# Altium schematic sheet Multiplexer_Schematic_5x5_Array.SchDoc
size D; SheetNumber: 1; SheetTotal: 1
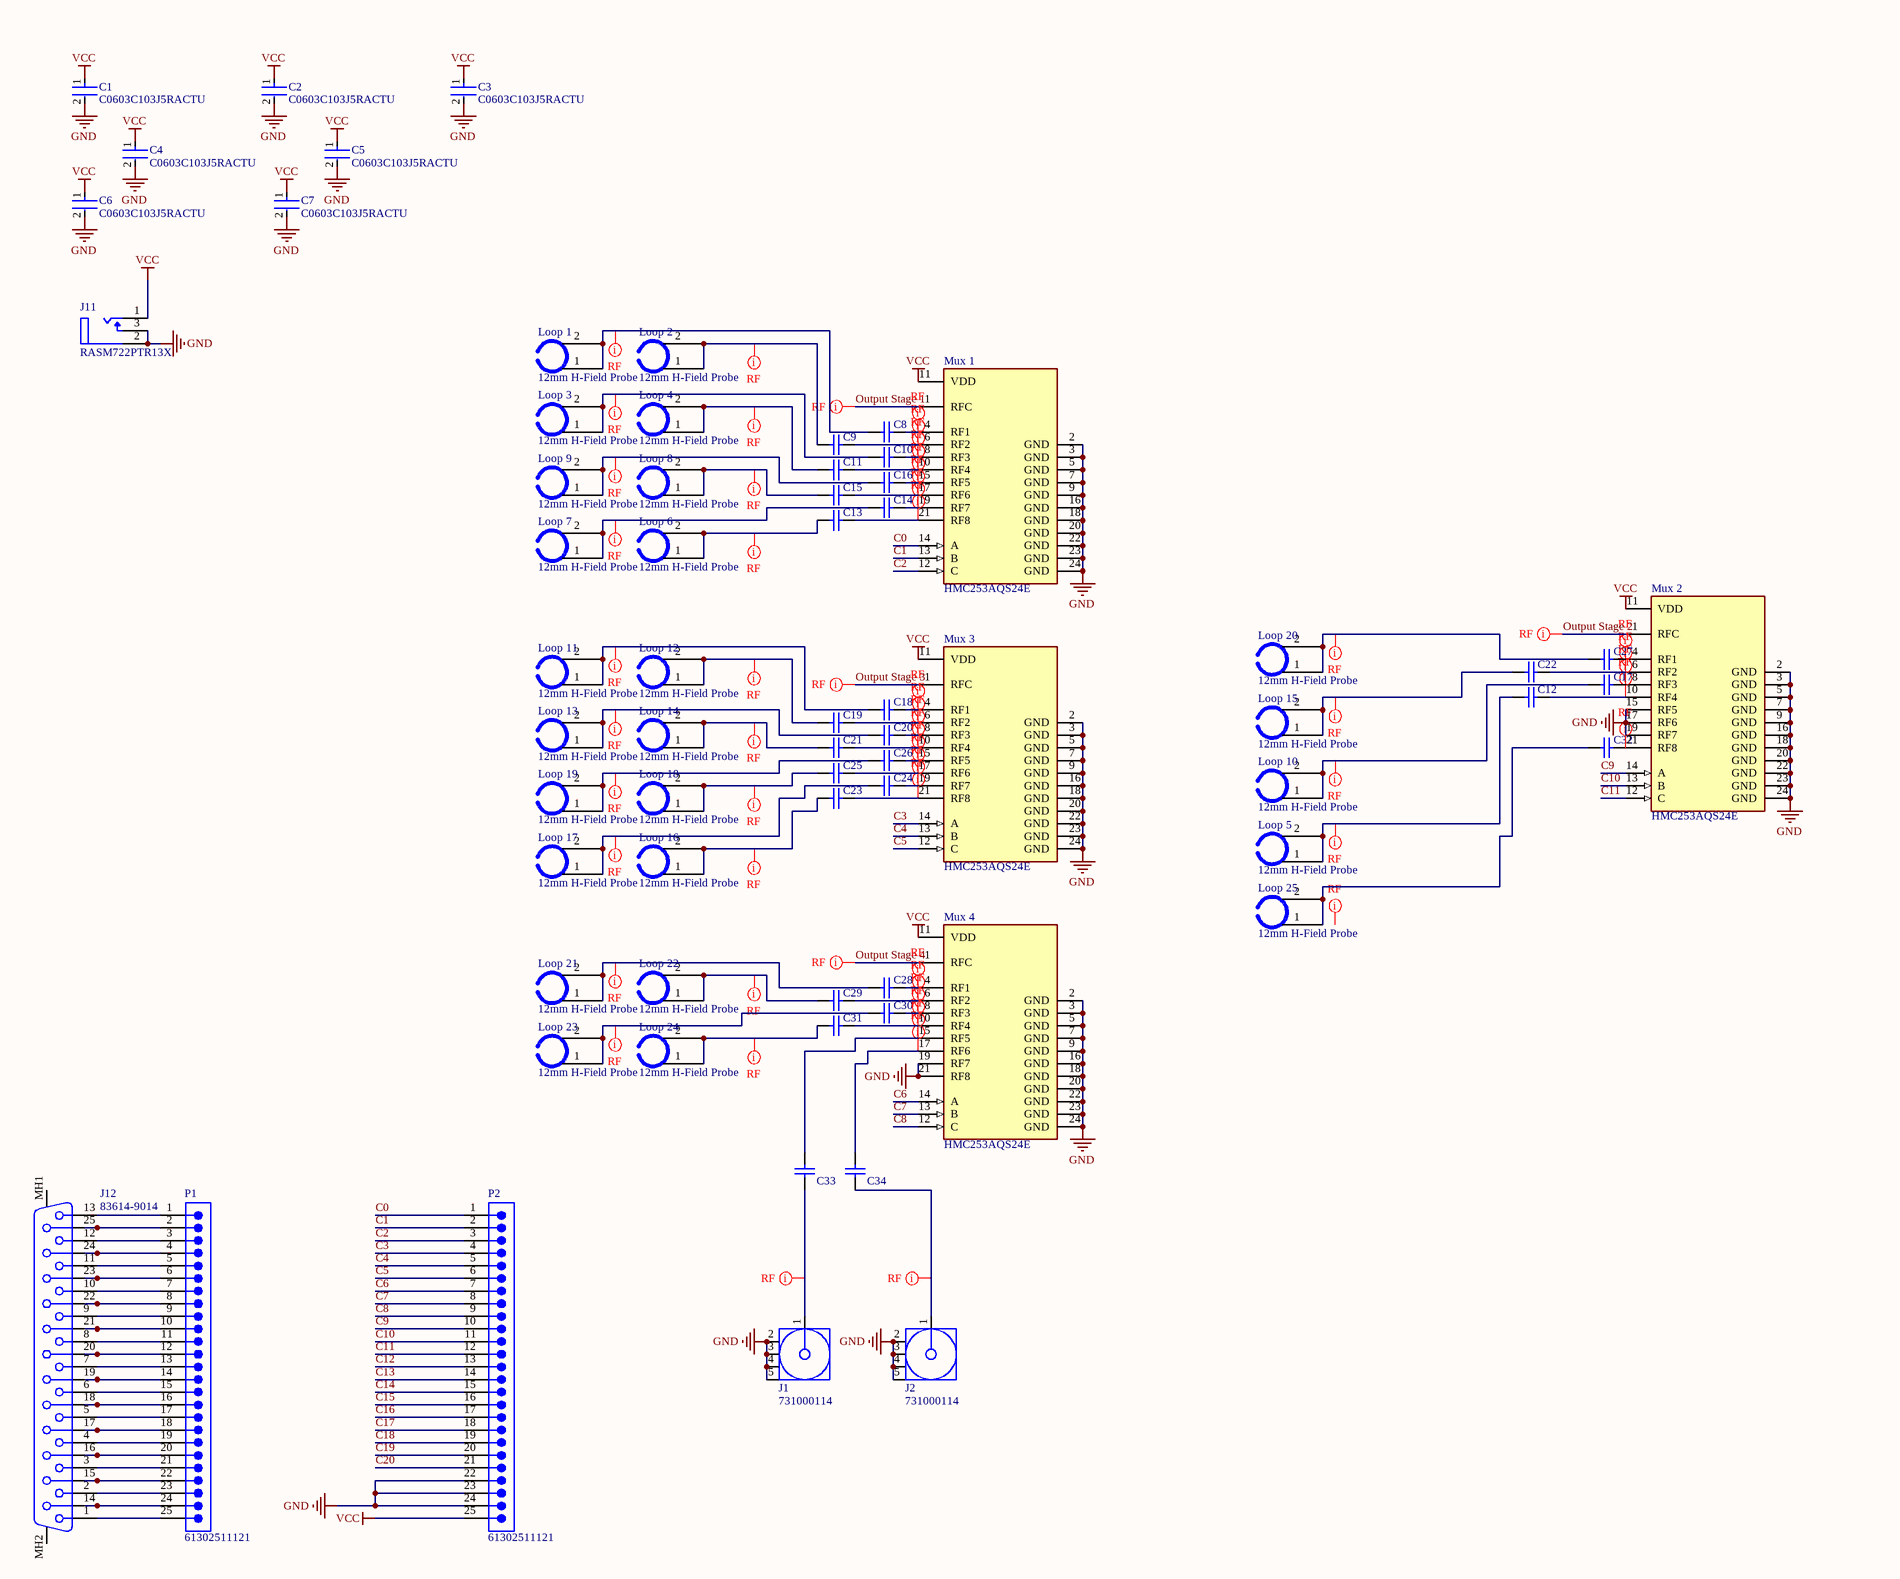
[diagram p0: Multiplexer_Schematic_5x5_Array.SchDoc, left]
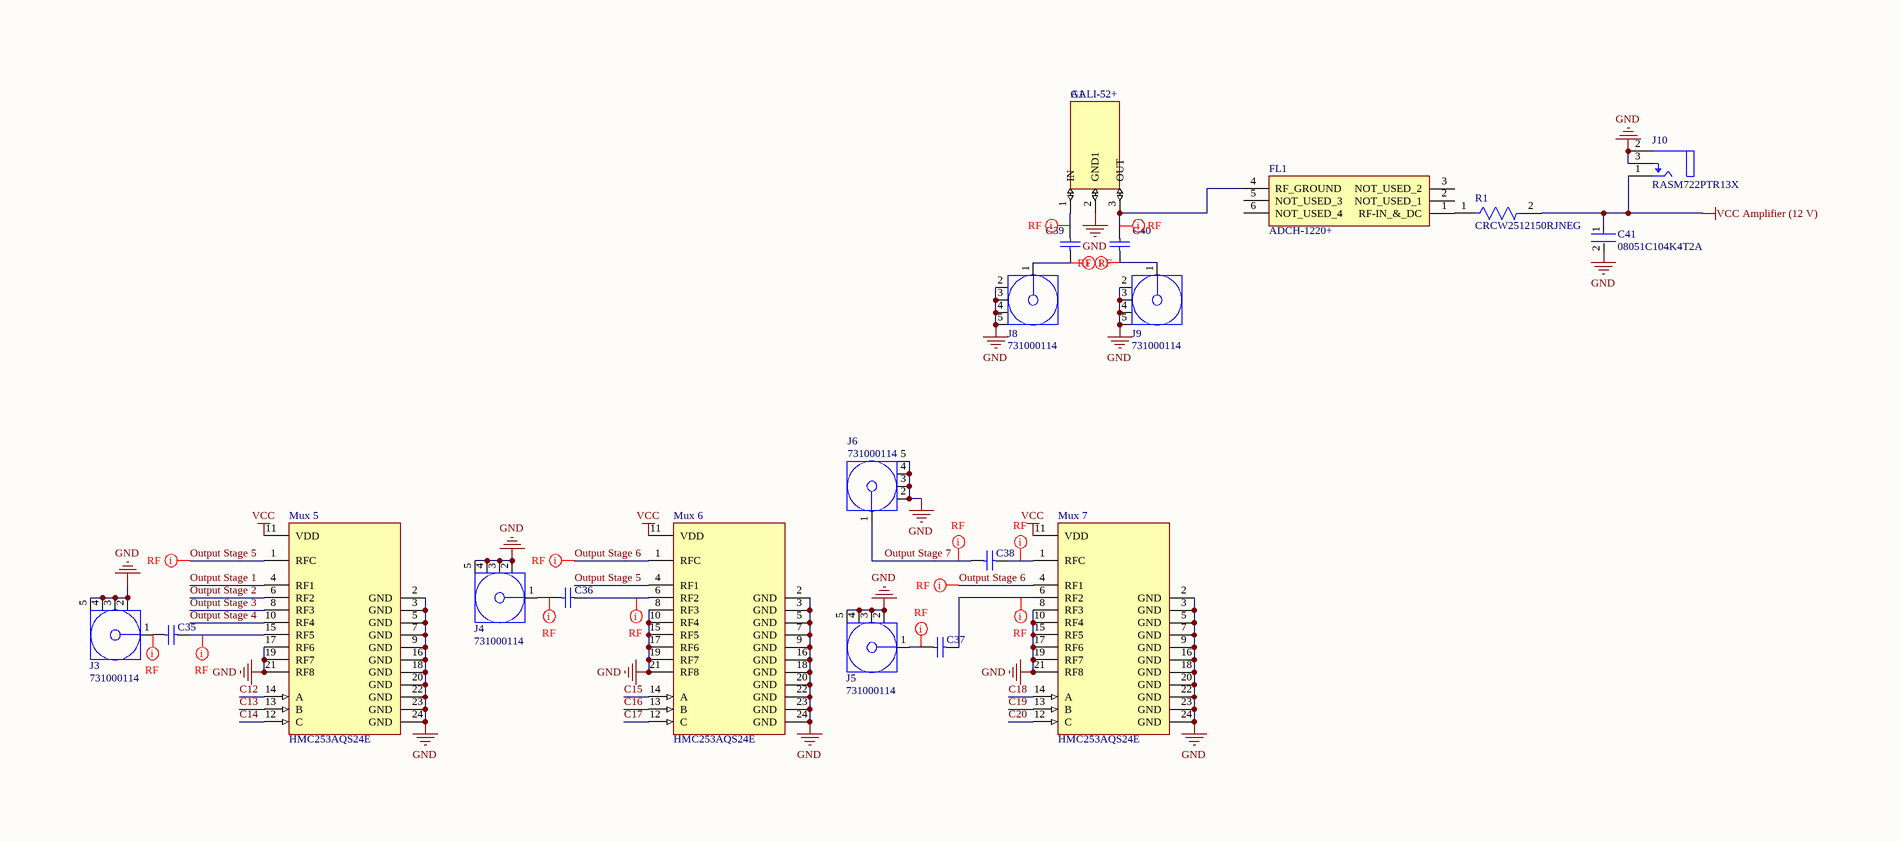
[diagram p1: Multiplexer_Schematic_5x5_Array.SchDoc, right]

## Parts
A1  GALI-52+  [GALI-52+]
C1  C0603C103J5RACTU  [FP-C0603C-CF-MFG]
C2  C0603C103J5RACTU  [FP-C0603C-CF-MFG]
C3  C0603C103J5RACTU  [FP-C0603C-CF-MFG]
C4  C0603C103J5RACTU  [FP-C0603C-CF-MFG]
C5  C0603C103J5RACTU  [FP-C0603C-CF-MFG]
C6  C0603C103J5RACTU  [FP-C0603C-CF-MFG]
C7  C0603C103J5RACTU  [FP-C0603C-CF-MFG]
C8  GRM1555C1H101JA01D  [CAPC1005X55X25ML05T10]  (value not drawn)
C9  GRM1555C1H101JA01D  [CAPC1005X55X25ML05T10]  (value not drawn)
C10  GRM1555C1H101JA01D  [CAPC1005X55X25ML05T10]  (value not drawn)
C11  GRM1555C1H101JA01D  [CAPC1005X55X25ML05T10]  (value not drawn)
C12  GRM1555C1H101JA01D  [CAPC1005X55X25ML05T10]  (value not drawn)
C13  GRM1555C1H101JA01D  [CAPC1005X55X25ML05T10]  (value not drawn)
C14  GRM1555C1H101JA01D  [CAPC1005X55X25ML05T10]  (value not drawn)
C15  GRM1555C1H101JA01D  [CAPC1005X55X25ML05T10]  (value not drawn)
C16  GRM1555C1H101JA01D  [CAPC1005X55X25ML05T10]  (value not drawn)
C17  GRM1555C1H101JA01D  [CAPC1005X55X25ML05T10]  (value not drawn)
C18  GRM1555C1H101JA01D  [CAPC1005X55X25ML05T10]  (value not drawn)
C19  GRM1555C1H101JA01D  [CAPC1005X55X25ML05T10]  (value not drawn)
C20  GRM1555C1H101JA01D  [CAPC1005X55X25ML05T10]  (value not drawn)
C21  GRM1555C1H101JA01D  [CAPC1005X55X25ML05T10]  (value not drawn)
C22  GRM1555C1H101JA01D  [CAPC1005X55X25ML05T10]  (value not drawn)
C23  GRM1555C1H101JA01D  [CAPC1005X55X25ML05T10]  (value not drawn)
C24  GRM1555C1H101JA01D  [CAPC1005X55X25ML05T10]  (value not drawn)
C25  GRM1555C1H101JA01D  [CAPC1005X55X25ML05T10]  (value not drawn)
C26  GRM1555C1H101JA01D  [CAPC1005X55X25ML05T10]  (value not drawn)
C27  GRM1555C1H101JA01D  [CAPC1005X55X25ML05T10]  (value not drawn)
C28  GRM1555C1H101JA01D  [CAPC1005X55X25ML05T10]  (value not drawn)
C29  GRM1555C1H101JA01D  [CAPC1005X55X25ML05T10]  (value not drawn)
C30  GRM1555C1H101JA01D  [CAPC1005X55X25ML05T10]  (value not drawn)
C31  GRM1555C1H101JA01D  [CAPC1005X55X25ML05T10]  (value not drawn)
C32  GRM1555C1H101JA01D  [CAPC1005X55X25ML05T10]  (value not drawn)
C33  GRM1555C1H101JA01D  [CAPC1005X55X25ML05T10]  (value not drawn)
C34  GRM1555C1H101JA01D  [CAPC1005X55X25ML05T10]  (value not drawn)
C35  GRM1555C1H101JA01D  [CAPC1005X55X25ML05T10]  (value not drawn)
C36  GRM1555C1H101JA01D  [CAPC1005X55X25ML05T10]  (value not drawn)
C37  GRM1555C1H101JA01D  [CAPC1005X55X25ML05T10]  (value not drawn)
C38  GRM1555C1H101JA01D  [CAPC1005X55X25ML05T10]  (value not drawn)
C39  GRM1555C1H101JA01D  [CAPC1005X55X25ML05T10]  (value not drawn)
C40  GRM1555C1H101JA01D  [CAPC1005X55X25ML05T10]  (value not drawn)
C41  08051C104K4T2A  [FP-0805-L_2_01_0_2-W_1_25-IPC_B]
FL1  ADCH-1220+  [ADCH1220]
J1  731000114  [MOLX-731000114_V]
J2  731000114  [MOLX-731000114_V]
J3  731000114  [MOLX-731000114_V]
J4  731000114  [MOLX-731000114_V]
J5  731000114  [MOLX-731000114_V]
J6  731000114  [MOLX-731000114_V]
J8  731000114  [MOLX-731000114_V]
J9  731000114  [MOLX-731000114_V]
J10  RASM722PTR13X  [FP-RASM722PTR13X-MFG]
J11  RASM722PTR13X  [FP-RASM722PTR13X-MFG]
J12  83614-9014  [836149014]
Loop_1  12mm H-Field Probe  [PCBComponent_1]
Loop_2  12mm H-Field Probe  [PCBComponent_1]
Loop_3  12mm H-Field Probe  [PCBComponent_1]
Loop_4  12mm H-Field Probe  [PCBComponent_1]
Loop_5  12mm H-Field Probe  [PCBComponent_1]
Loop_6  12mm H-Field Probe  [PCBComponent_1]
Loop_7  12mm H-Field Probe  [PCBComponent_1]
Loop_8  12mm H-Field Probe  [PCBComponent_1]
Loop_9  12mm H-Field Probe  [PCBComponent_1]
Loop_10  12mm H-Field Probe  [PCBComponent_1]
Loop_11  12mm H-Field Probe  [PCBComponent_1]
Loop_12  12mm H-Field Probe  [PCBComponent_1]
Loop_13  12mm H-Field Probe  [PCBComponent_1]
Loop_14  12mm H-Field Probe  [PCBComponent_1]
Loop_15  12mm H-Field Probe  [PCBComponent_1]
Loop_16  12mm H-Field Probe  [PCBComponent_1]
Loop_17  12mm H-Field Probe  [PCBComponent_1]
Loop_18  12mm H-Field Probe  [PCBComponent_1]
Loop_19  12mm H-Field Probe  [PCBComponent_1]
Loop_20  12mm H-Field Probe  [PCBComponent_1]
Loop_21  12mm H-Field Probe  [PCBComponent_1]
Loop_22  12mm H-Field Probe  [PCBComponent_1]
Loop_23  12mm H-Field Probe  [PCBComponent_1]
Loop_24  12mm H-Field Probe  [PCBComponent_1]
Loop_25  12mm H-Field Probe  [PCBComponent_1]
Mux_1  HMC253AQS24E  [FP-QS24E-MFG]
Mux_2  HMC253AQS24E  [FP-QS24E-MFG]
Mux_3  HMC253AQS24E  [FP-QS24E-MFG]
Mux_4  HMC253AQS24E  [FP-QS24E-MFG]
Mux_5  HMC253AQS24E  [FP-QS24E-MFG]
Mux_6  HMC253AQS24E  [FP-QS24E-MFG]
Mux_7  HMC253AQS24E  [FP-QS24E-MFG]
P1  61302511121  [61302511121]
P2  61302511121  [61302511121]
R1  CRCW2512150RJNEG  [FP-CRCW2512-e3-IPC_B]

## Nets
GND: A1.2(GND1) C1.2 C2.2 C3.2 C4.2 C5.2 C6.2 C7.2 C41.2 J1.2 J1.3 J1.4 J1.5 J2.2 J2.3 J2.4 J2.5 J3.2 J3.3 J3.4 J3.5 J4.2 J4.3 J4.4 J4.5 J5.2 J5.3 J5.4 J5.5 J6.2 J6.3 J6.4 J6.5 J8.2 J8.3 J8.4 J8.5 J9.2 J9.3 J9.4 J9.5 J10.2(SLEEVE_TERMINAL) J10.3(SHUNT_TERMINAL) J11.2(SLEEVE_TERMINAL) J11.3(SHUNT_TERMINAL) Mux_1.2(GND) Mux_1.3(GND) Mux_1.5(GND) Mux_1.7(GND) Mux_1.9(GND) Mux_1.16(GND) Mux_1.18(GND) Mux_1.20(GND) Mux_1.22(GND) Mux_1.23(GND) Mux_1.24(GND) Mux_2.2(GND) Mux_2.3(GND) Mux_2.5(GND) Mux_2.7(GND) Mux_2.9(GND) Mux_2.15(RF5) Mux_2.16(GND) Mux_2.17(RF6) Mux_2.18(GND) Mux_2.19(RF7) Mux_2.20(GND) Mux_2.22(GND) Mux_2.23(GND) Mux_2.24(GND) Mux_3.2(GND) Mux_3.3(GND) Mux_3.5(GND) Mux_3.7(GND) Mux_3.9(GND) Mux_3.16(GND) Mux_3.18(GND) Mux_3.20(GND) Mux_3.22(GND) Mux_3.23(GND) Mux_3.24(GND) Mux_4.2(GND) Mux_4.3(GND) Mux_4.5(GND) Mux_4.7(GND) Mux_4.9(GND) Mux_4.16(GND) Mux_4.18(GND) Mux_4.19(RF7) Mux_4.20(GND) Mux_4.21(RF8) Mux_4.22(GND) Mux_4.23(GND) Mux_4.24(GND) Mux_5.2(GND) Mux_5.3(GND) Mux_5.5(GND) Mux_5.7(GND) Mux_5.9(GND) Mux_5.16(GND) Mux_5.17(RF6) Mux_5.18(GND) Mux_5.19(RF7) Mux_5.20(GND) Mux_5.21(RF8) Mux_5.22(GND) Mux_5.23(GND) Mux_5.24(GND) Mux_6.2(GND) Mux_6.3(GND) Mux_6.5(GND) Mux_6.7(GND) Mux_6.8(RF3) Mux_6.9(GND) Mux_6.10(RF4) Mux_6.15(RF5) Mux_6.16(GND) Mux_6.17(RF6) Mux_6.18(GND) Mux_6.19(RF7) Mux_6.20(GND) Mux_6.21(RF8) Mux_6.22(GND) Mux_6.23(GND) Mux_6.24(GND) Mux_7.2(GND) Mux_7.3(GND) Mux_7.5(GND) Mux_7.7(GND) Mux_7.8(RF3) Mux_7.9(GND) Mux_7.10(RF4) Mux_7.15(RF5) Mux_7.16(GND) Mux_7.17(RF6) Mux_7.18(GND) Mux_7.19(RF7) Mux_7.20(GND) Mux_7.21(RF8) Mux_7.22(GND) Mux_7.23(GND) Mux_7.24(GND) P2.22 P2.23 P2.24
VCC: C1.1 C2.1 C3.1 C4.1 C5.1 C6.1 C7.1 J11.1(TIP_TERMINAL(CENTER_PIN)) Mux_1.11(VDD) Mux_2.11(VDD) Mux_3.11(VDD) Mux_4.11(VDD) Mux_5.11(VDD) Mux_6.11(VDD) Mux_7.11(VDD) P2.25
VCC Amplifier (12 V): C41.1 J10.1(TIP_TERMINAL(CENTER_PIN)) R1.2
C0: Mux_1.14(A) P2.1
C1: Mux_1.13(B) P2.2
C2: Mux_1.12(C) P2.3
C3: Mux_3.14(A) P2.4
C4: Mux_3.13(B) P2.5
C5: Mux_3.12(C) P2.6
C6: Mux_4.14(A) P2.7
C7: Mux_4.13(B) P2.8
C8: Mux_4.12(C) P2.9
C9: Mux_2.14(A) P2.10
C10: Mux_2.13(B) P2.11
C11: Mux_2.12(C) P2.12
C12: Mux_5.14(A) P2.13
C13: Mux_5.13(B) P2.14
C14: Mux_5.12(C) P2.15
C15: Mux_6.14(A) P2.16
C16: Mux_6.13(B) P2.17
C17: Mux_6.12(C) P2.18
C18: Mux_7.14(A) P2.19
C19: Mux_7.13(B) P2.20
C20: Mux_7.12(C) P2.21
Output Stage 1: Mux_1.1(RFC) Mux_5.4(RF1)
Output Stage 2: Mux_2.1(RFC) Mux_5.6(RF2)
Output Stage 3: Mux_3.1(RFC) Mux_5.8(RF3)
Output Stage 4: Mux_4.1(RFC) Mux_5.10(RF4)
Output Stage 5: Mux_5.1(RFC) Mux_6.4(RF1)
Output Stage 6: Mux_6.1(RFC) Mux_7.4(RF1)
Output Stage 7: C38.1 J6.1
NetA1_1: A1.1(IN) C39.2
NetA1_3: A1.3(OUT) C40.2 FL1.4(RF_GROUND)
NetC8_1: C8.1 Loop_1.1 Loop_1.2
NetC8_2: C8.2 Mux_1.4(RF1)
NetC9_1: C9.1 Loop_2.1 Loop_2.2
NetC9_2: C9.2 Mux_1.6(RF2)
NetC10_1: C10.1 Loop_3.1 Loop_3.2
NetC10_2: C10.2 Mux_1.8(RF3)
NetC11_1: C11.1 Loop_4.1 Loop_4.2
NetC11_2: C11.2 Mux_1.10(RF4)
NetC12_1: C12.1 Loop_5.1 Loop_5.2
NetC12_2: C12.2 Mux_2.10(RF4)
NetC13_1: C13.1 Loop_6.1 Loop_6.2
NetC13_2: C13.2 Mux_1.21(RF8)
NetC14_1: C14.1 Loop_7.1 Loop_7.2
NetC14_2: C14.2 Mux_1.19(RF7)
NetC15_1: C15.1 Loop_8.1 Loop_8.2
NetC15_2: C15.2 Mux_1.17(RF6)
NetC16_1: C16.1 Loop_9.1 Loop_9.2
NetC16_2: C16.2 Mux_1.15(RF5)
NetC17_1: C17.1 Loop_10.1 Loop_10.2
NetC17_2: C17.2 Mux_2.8(RF3)
NetC18_1: C18.1 Loop_11.1 Loop_11.2
NetC18_2: C18.2 Mux_3.4(RF1)
NetC19_1: C19.1 Loop_12.1 Loop_12.2
NetC19_2: C19.2 Mux_3.6(RF2)
NetC20_1: C20.1 Loop_13.1 Loop_13.2
NetC20_2: C20.2 Mux_3.8(RF3)
NetC21_1: C21.1 Loop_14.1 Loop_14.2
NetC21_2: C21.2 Mux_3.10(RF4)
NetC22_1: C22.1 Loop_15.1 Loop_15.2
NetC22_2: C22.2 Mux_2.6(RF2)
NetC23_1: C23.1 Loop_16.1 Loop_16.2
NetC23_2: C23.2 Mux_3.21(RF8)
NetC24_1: C24.1 Loop_17.1 Loop_17.2
NetC24_2: C24.2 Mux_3.19(RF7)
NetC25_1: C25.1 Loop_18.1 Loop_18.2
NetC25_2: C25.2 Mux_3.17(RF6)
NetC26_1: C26.1 Loop_19.1 Loop_19.2
NetC26_2: C26.2 Mux_3.15(RF5)
NetC27_1: C27.1 Loop_20.1 Loop_20.2
NetC27_2: C27.2 Mux_2.4(RF1)
NetC28_1: C28.1 Loop_21.1 Loop_21.2
NetC28_2: C28.2 Mux_4.4(RF1)
NetC29_1: C29.1 Loop_22.1 Loop_22.2
NetC29_2: C29.2 Mux_4.6(RF2)
NetC30_1: C30.1 Loop_23.1 Loop_23.2
NetC30_2: C30.2 Mux_4.8(RF3)
NetC31_1: C31.1 Loop_24.1 Loop_24.2
NetC31_2: C31.2 Mux_4.10(RF4)
NetC32_1: C32.1 Loop_25.1 Loop_25.2
NetC32_2: C32.2 Mux_2.21(RF8)
NetC33_1: C33.1 J1.1
NetC33_2: C33.2 Mux_4.15(RF5)
NetC34_1: C34.1 J2.1
NetC34_2: C34.2 Mux_4.17(RF6)
NetC35_1: C35.1 J3.1
NetC35_2: C35.2 Mux_5.15(RF5)
NetC36_1: C36.1 J4.1
NetC36_2: C36.2 Mux_6.6(RF2)
NetC37_1: C37.1 J5.1
NetC37_2: C37.2 Mux_7.6(RF2)
NetC38_2: C38.2 Mux_7.1(RFC)
NetC39_1: C39.1 J8.1
NetC40_1: C40.1 J9.1
NetFL1_1: FL1.1(RF-IN_&_DC) R1.1
NetJ12_1: J12.1 P1.25
NetJ12_2: J12.2 P1.23
NetJ12_3: J12.3 P1.21
NetJ12_4: J12.4 P1.19
NetJ12_5: J12.5 P1.17
NetJ12_6: J12.6 P1.15
NetJ12_7: J12.7 P1.13
NetJ12_8: J12.8 P1.11
NetJ12_9: J12.9 P1.9
NetJ12_10: J12.10 P1.7
NetJ12_11: J12.11 P1.5
NetJ12_12: J12.12 P1.3
NetJ12_13: J12.13 P1.1
NetJ12_14: J12.14 P1.24
NetJ12_15: J12.15 P1.22
NetJ12_16: J12.16 P1.20
NetJ12_17: J12.17 P1.18
NetJ12_18: J12.18 P1.16
NetJ12_19: J12.19 P1.14
NetJ12_20: J12.20 P1.12
NetJ12_21: J12.21 P1.10
NetJ12_22: J12.22 P1.8
NetJ12_23: J12.23 P1.6
NetJ12_24: J12.24 P1.4
NetJ12_25: J12.25 P1.2

Not connected (* = marked no-connect by the designer): FL1 2(NOT_USED_1) 3(NOT_USED_2) 5(NOT_USED_3) 6(NOT_USED_4); J12 MH1 MH2

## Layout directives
net class RF: (no net found under the mark), NetA1_1, NetA1_3, NetC8_1, NetC8_2, NetC9_1, NetC9_2, NetC10_1, NetC10_2, NetC11_1, NetC11_2, NetC12_1, NetC12_2, NetC13_1, NetC13_2, NetC14_1, NetC14_2, NetC15_1, NetC15_2, NetC16_1, NetC16_2, NetC17_1, NetC17_2, NetC18_1, NetC18_2, NetC19_1, NetC19_2, NetC20_1, NetC20_2, NetC21_1, NetC21_2, NetC22_1, NetC22_2, NetC23_1, NetC23_2, NetC24_1, NetC24_2, NetC25_1, NetC25_2, NetC26_1, NetC26_2, NetC27_1, NetC27_2, NetC28_1, NetC28_2, NetC29_1, NetC29_2, NetC30_1, NetC30_2, NetC31_1, NetC31_2, NetC32_2, NetC33_1, NetC33_2, NetC34_1, NetC34_2, NetC35_1, NetC35_2, NetC36_1, NetC36_2, NetC37_1, NetC37_2, NetC38_2, NetC39_1, NetC40_1, Output Stage 1, Output Stage 2, Output Stage 3, Output Stage 4, Output Stage 5, Output Stage 6, Output Stage 7

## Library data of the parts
A1 = GALI-52+: RF Amplifier SMT Low Noise Amplifier, DC - 2000 MHz, 50; MF: Mini-Circuits
C1-C7 = CMP-2006-03817-3: Capacitor; Ceramic; Cap; .010uF; Tol 5%; SMT; Vol-Rtg 50V; X7R; Tape and Reel; Manufacturer: KEMET; Value: 10,000 pF; Automotive Grade: Grade 1; Temperature Coefficient: 30ppm/°C; Tolerance: 0.05
C8-C40 = CMP-2008-03915-1: Manufacturer: Murata
C41 = CMP-2007-04172-2: Automotive Ceramic Capacitor, 0805, 100nF, 10%, X7R, 15%, 100V
FL1 = ADCH-1220+: Filter; Manufacturer_Name: Mini-Circuits
J1-J6 J8 J9 = CMP-2000-05487-1: SMA Right-Angle PCB Jack Receptacle, Brass Body, Gold Plated, 50 Ohm, 5-Pin THD, RoHS, Tray; Manufacturer: Molex
J10 J11 = CMP-47995-000002-1: CONN PWR JACK 2.1X5.5MM SOLDER; Shielding: Unshielded; Gender: Male; Current Rating: 5A
J12 = 83614-9014: Connector; Manufacturer_Name: Molex
Mux_1-Mux_7 = CMP-09141-000040-1: IC RF SWITCH SP8T 2.5GHZ 24QSOP; Test Frequency: 1GHz; IIP3: 46dBm; Impedance: 50R; Insertion Loss: 1dB; P1dB: 23dBm
P1 P2 = CMP-1502-01112-2: NexarPartId: 32855564; Pitch: 2.54mm; Gender: Male; Operating Supply Voltage: 250V; Current Rating: 3A; Contact Resistance: 20mΩ; Number of Positions: 25; Connector Type: Male Pin
R1 = CMP-02407-002320-1: RES Thick Film, 150Ω, 5%, 1W, 200ppm/°C, 2512; Voltage Rating: 500V; Resistance: 150R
